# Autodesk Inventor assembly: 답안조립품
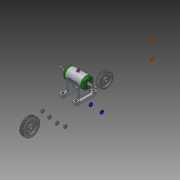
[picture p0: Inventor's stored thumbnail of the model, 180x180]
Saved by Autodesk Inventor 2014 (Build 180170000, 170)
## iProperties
Created: 2015-11
Part Number: 답안조립품
Document SubType Name: Assembly
Designer: USER
Author: USER
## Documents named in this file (16)
- C:\Users\USER\Desktop\451109V1015\답안조립품.iam
- C:\Users\USER\Desktop\451109V1015\V벨트풀리.ipt
- C:\Users\USER\Desktop\451109V1015\너트 M 8.ipt
- C:\Users\USER\Desktop\451109V1015\니플 M 6 x 0.75.ipt
- C:\Users\USER\Desktop\451109V1015\베어링 15 x 32 x 9.ipt
- C:\Users\USER\Desktop\451109V1015\본체.ipt
- C:\Users\USER\Desktop\451109V1015\볼트 M 6 x 8.ipt
- C:\Users\USER\Desktop\451109V1015\볼트 M4 x 12.ipt
- C:\Users\USER\Desktop\451109V1015\스퍼기어.ipt
- C:\Users\USER\Desktop\451109V1015\스프링와셔 8.ipt
- C:\Users\USER\Desktop\451109V1015\오일 실 15 25 7.ipt
- C:\Users\USER\Desktop\451109V1015\와셔 6x11.5.ipt
- C:\Users\USER\Desktop\451109V1015\와셔 8x17.ipt
- C:\Users\USER\Desktop\451109V1015\축.ipt
- C:\Users\USER\Desktop\451109V1015\커버.ipt
- C:\Users\USER\Desktop\451109V1015\키 3 x 3 x 12.ipt
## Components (11 placed, 3 different names)
1. V벨트풀리:1
2. KS B 2023 6002 - 15 x 32 x 9:1
3. KS B 2023 6002 - 15 x 32 x 9:2
4. ISO 4762 M4 x 12:2
5. ISO 4762 M4 x 12:3
6. ISO 4762 M4 x 12:4
7. ISO 4762 M4 x 12:5
8. ISO 4762 M4 x 12:1
9. ISO 4762 M4 x 12:6
10. ISO 4762 M4 x 12:7
11. ISO 4762 M4 x 12:8
